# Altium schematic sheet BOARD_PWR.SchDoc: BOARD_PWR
size A4; Date: Not used; ApprovedBy: Not used; CheckedBy: Not used; Author: Not used; CompanyName: STMicroelectronics; DrawnBy: Not used; Engineer: Not used; Organization: Not used; Address1: Not used; Address2: Not used; Address3: Not used; Address4: Not used; DocumentNumber: 14; Revision: Not used; SheetNumber: 14; SheetTotal: 16
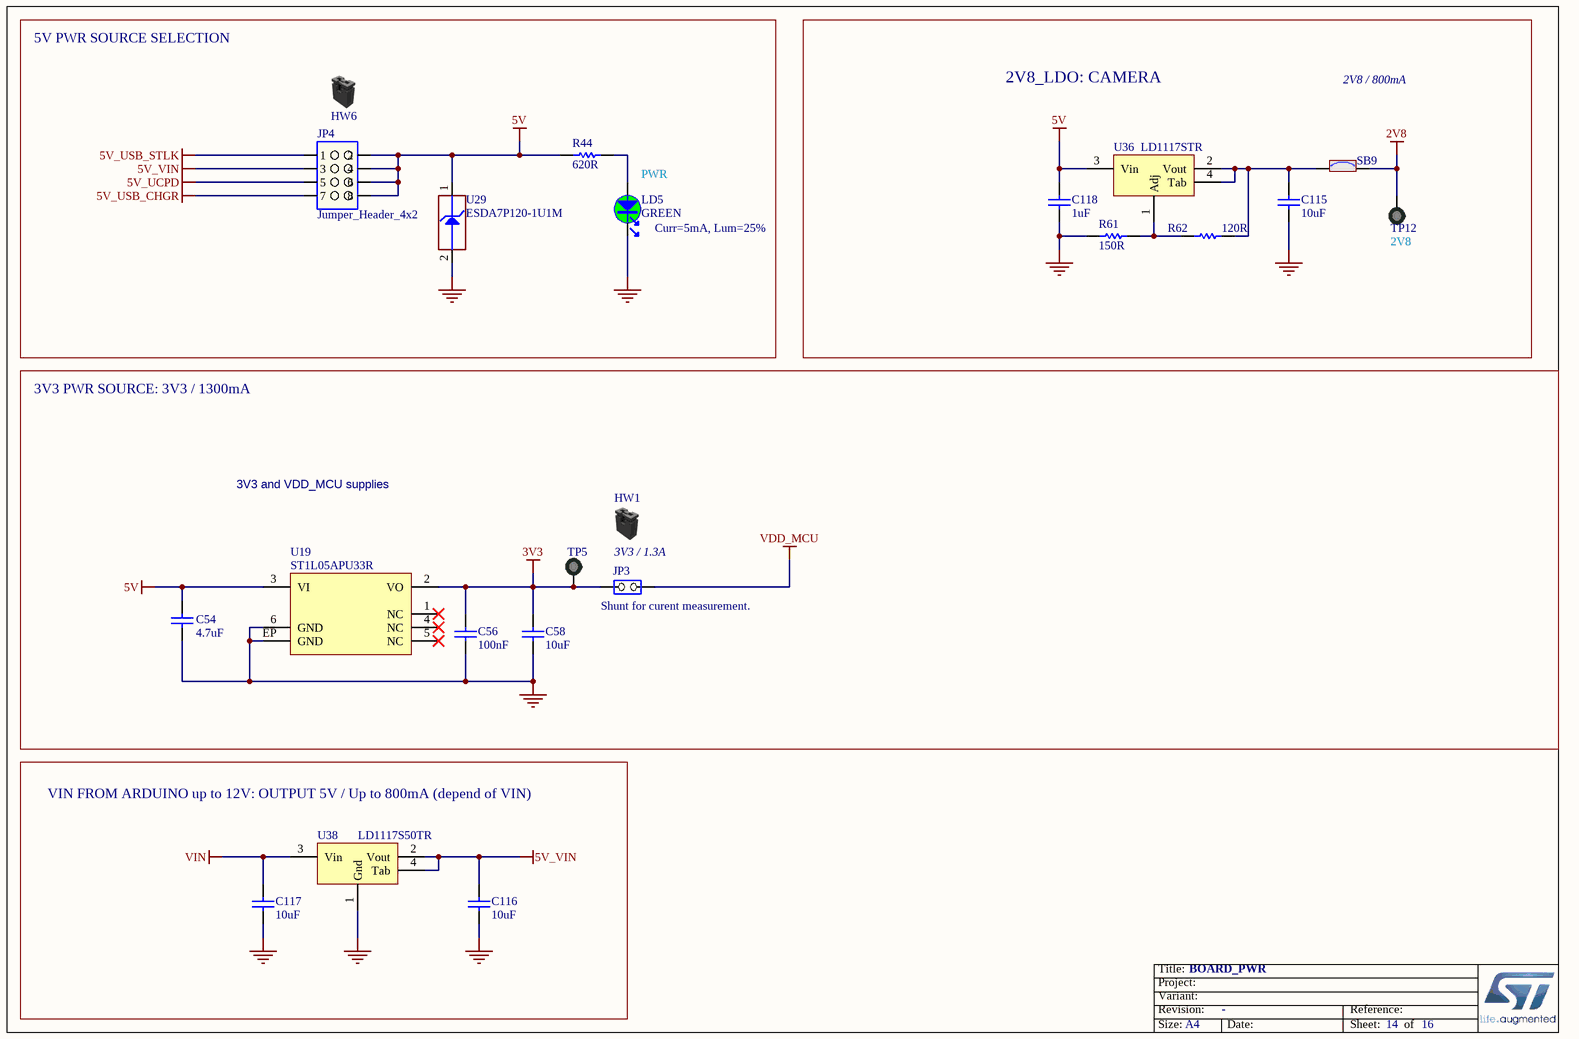
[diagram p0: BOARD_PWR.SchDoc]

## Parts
C54  value 4.7uF  [C0603]
C56  value 100nF  [C0402]
C58  value 10uF  [C0805]  (hidden comment: Capacitor)
C115  value 10uF  [C0402]  (hidden comment: Capacitor)
C116  value 10uF  [C0603]  (hidden comment: Capacitor)
C117  value 10uF  [C0603]  (hidden comment: Capacitor)
C118  value 1uF  [C0603]
HW1  Shunt Black 2.54mm  (value not drawn)  (mechanical)
HW6  (no value)  (mechanical)
JP3  value Shunt for curent measurement.  [CON_SAMTEC_TSW-102-07-G-S]  (hidden comment: Jumper_Header 2x1)
JP4  value Jumper_Header_4x2  [CON_SAMTEC_TSW-104-07-X-D]  (hidden comment: Jumper_Header 4x2)
LD5  value GREEN  [LED_0603_OSRAM_LG-Q396-PS-35_GREEN_1A2K_H0P4]
R44  value 620R  [R0402]
R61  value 150R  [R0603]
R62  value 120R  [R0603]  (hidden comment: Resistor)
SB9  (no value)  [SOLDER-BRIDGE_R0603-0R]
TP5  (no value)  [TP_PTH_1MM_2MM]  (no BOM)
TP12  value 2V8  [TP_PTH_1MM_2MM]  (no BOM)
U19  ST1L05APU33R  [ICC_DFN6-EPAD_3X3_P095]
U29  value ESDA7P120-1U1M  [ESD_QFN1610_2N_1K_2A]  (hidden comment: ESD-TRANSIL)
U36  value LD1117STR  [REG_SOT223-TAB]
U38  LD1117S50TR  [REG_SOT223-TAB]

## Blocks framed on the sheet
5V PWR SOURCE SELECTION: HW6 JP4 LD5 R44 U29
2V8_LDO: CAMERA: C115 C118 R61 R62 SB9 TP12 U36
3V3 PWR SOURCE: 3V3 / 1300mA: C54 C56 C58 HW1 JP3 TP5 U19

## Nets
2V8: SB9.2 TP12.1
3V3: C56.1 C58.2 JP3.2(NO) TP5.1 U19.2(VO)
5V: C54.2 C118.2 JP4.2 JP4.4 JP4.6 JP4.8 R44.2 U19.3(VI) U29.1(IO1) U36.3(Vin)
5V_UCPD: JP4.5
5V_USB_CHGR: JP4.7
5V_USB_STLK: JP4.1
5V_VIN: C116.2 JP4.3 U38.2(Vout) U38.4(Tab)
GND: C54.1 C56.2 C58.1 C115.1 C116.1 C117.1 C118.1 LD5.2 R61.1 U19.6(GND) U19.EP(GND) U29.2(GND) U38.1(Gnd)
VDD_MCU: JP3.1(COMMON)
VIN: C117.2 U38.3(Vin)
NetC115_2: C115.2 R62.2 SB9.1 U36.2(Vout) U36.4(Tab)
NetLD5_1: LD5.1 R44.1
NetR61_2: R61.2 R62.1 U36.1(Adj)

Not connected (* = marked no-connect by the designer): U19 1(NC)* 4(NC)* 5(NC)*

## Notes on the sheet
- 2V8 / 800mA
- (near LD5) PWR
- (near LD5) Curr=5mA, Lum=25%
- 3V3 and VDD_MCU supplies
- 3V3 / 1.3A
- VIN FROM ARDUINO up to 12V: OUTPUT 5V / Up to 800mA (depend of VIN)

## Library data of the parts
C54 = MCD-00009: Capacitor, MLCC, 4.7uF, 16V, X5R, 10%, 0603, T=0.8mm; Manufacturer_Part_Number: CC0603KRX5R7BB475; Manufacturer: YAGEO; ECCN_US: EAR99; ECCN_EU: NEC; Provided_By: SUBCO
C56 = MCD-00006: Capacitor, MLCC, 100nF, 16V, X7R, 10%, 0402, T=0.5mm; Manufacturer_Part_Number: CC0402KRX7R7BB104; Manufacturer: YAGEO; Alternate_Manufacturer_Part_Number: GCM155R71C104KA55D; Alternate_Manufacturer: MURATA; Provided_By: SUBCO; ECCN_US: EAR99; ECCN_EU: NEC
C58 = MCD-00014: Capacitor, MLCC, 10uF, 25V, X5R, 10%, 0805, T=0,85mm; Manufacturer_Part_Number: CC0805KRX5R8BB106; Manufacturer: YAGEO; Provided_By: SUBCO
C115 = MCD-01355: Capacitor, MLCC, 10uF, 4V, X5R, 20%, 0402, T=0,5mm; Manufacturer_Part_Number: GRM155R60G106ME44; Manufacturer: MURATA; ECCN_US: EAR99; ECCN_EU: NEC; Provided_By: Subcon; Initial_Board_Reference: MB1372
C116 C117 = MCD-00099: Capacitor, MLCC, 10uF, 10V, X5R, 10%, 0603, T=0,8mm; Manufacturer_Part_Number: GRM188R61A106KE69D; Manufacturer: MURATA; Provided_By: SUBCO; Initial_Board_Reference: MB1262; Item Type: Item; Path: ws/MCD_ApplicationBoards/Lists/MCDPARTSdatabase
C118 = MCD-00010: Capacitor, MLCC, 1uF, 16V, X5R, 10%, 0603, T=0,8mm; Manufacturer_Part_Number: CC0603KRX5R7BB105; Manufacturer: YAGEO; Provided_By: Subcon; Initial_Board_Reference: MB1274
HW1 = MCD-00043: SHUNT 2.54mm BLACK; Manufacturer_Part_Number: SNT-100-BK-G; Manufacturer: SAMTEC; Part_Type: Mechanical; Provided_By: Subcon; Initial_Board_Reference: MB1274
HW6 = MCD-00043: SHUNT 2.54mm BLACK; Part_Type: Mechanical; Manufacturer_Part_Number: SNT-100-BK-G; Manufacturer: SAMTEC; Provided_By: Subcon; Initial_Board_Reference: MB1274
JP3 = MCD-00045: Header, 2x1, 2,54mm, VR, TH, Height 5.84mm/2.54mm; Part_Type: Connector; Manufacturer_Part_Number: TSW-102-07-x-S; Manufacturer: SAMTEC; Provided_By: Subcon; Initial_Board_Reference: MB1274; Remark: 3D KO: BZ: 40098
JP4 = MCD-00633: Header, 4x2, 2,54mm, VR, TH, Height 5.84mm/2.54mm; Part_Type: Connector; Manufacturer_Part_Number: TSW-104-07-x-D; Manufacturer: SAMTEC; Provided_By: SUBCO
LD5 = MCD-00588: LED Green, 0603 SMD, Forward Voltage Typ=2V, Max=2.5V; Part_Type: Display; Manufacturer_Part_Number: LG Q396-PS-35; Manufacturer: OSRAM OPTO SEMICONDUCTORS; Alternate_Manufacturer_Part_Number: VLMTG1300-GS08; Alternate_Manufacturer: VISHAY SEMICONDUCTOR OPTO DIVISION; Provided_By: Subcon; Initial_Board_Reference: MB1331
R44 = MCD-00499: Resistor,620R,0402,1%,1/16W; Manufacturer_Part_Number: RC0402FR-07620RL; Manufacturer: YAGEO; Provided_By: Subcon
R61 = MCD-00394: Resistor,150,0603,1%,1/10W; Manufacturer_Part_Number: RC0603FR-07150RL; Manufacturer: YAGEO; ECCN_US: EAR99; ECCN_EU: NEC; Provided_By: SUBCO
R62 = MCD-00338: Resistor,120R,0603,1%,1/10W; Manufacturer_Part_Number: RC0603FR-07120RL; Manufacturer: YAGEO; BMS_Part_Number: 9129734; ECCN_US: EAR99; ECCN_EU: NEC; Provided_By: SUBCO
SB9 = MCD-00071: Solder Bridge ON; Part_Type: Mechanical; Provided_By: Subcon; Initial_Board_Reference: MB1274
TP5 TP12 = MCD-01506: Test Point trought hole 1mm/2mm; Part_Type: Mechanical; Initial_Board_Reference: MB1372; Item Type: Item; Path: ws/MCD_ApplicationBoards/Lists/MCDPARTSdatabase
U19 = MCD-01127: IC REG LDO 3.3V 1.3A 6DFN; Manufacturer: STMICROELECTRONICS; BMS_Part_Number: 9176247; Provided_By: SUBCO with ST control
U29 = MCD-01026: High power transient voltage suppressor; Part_Type: Diode; Manufacturer: STMICROELECTRONICS; Provided_By: SUBCO with ST control; Initial_Board_Reference: MB1378; Remark: Footprint moved fromROU lib: DFN105P160X60-2N to global-lib: ESD_QFN1610_2N_1K_2A; Item Type: Item; Path: ws/MCD_ApplicationBoards/Lists/MCDPARTSdatabase
U36 = MCD-00721: LDO Voltage Regulator, Adjustable, 15V in, 1.1V drop, 1.25V to 15V/0.8A out, SOT-223-3; Part_Type: IC; Manufacturer: STMICROELECTRONICS; BMS_Part_Number: 9176132; ECCN_US: EAR99; ECCN_EU: NEC; Provided_By: SUBCO with ST control
U38 = MCD-00088: IC REG LDO 5V 0.8A SOT223; Manufacturer: STMICROELECTRONICS; ECCN_US: EAR99; ECCN_EU: NEC; Provided_By: Subcon; Initial_Board_Reference: MB1274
